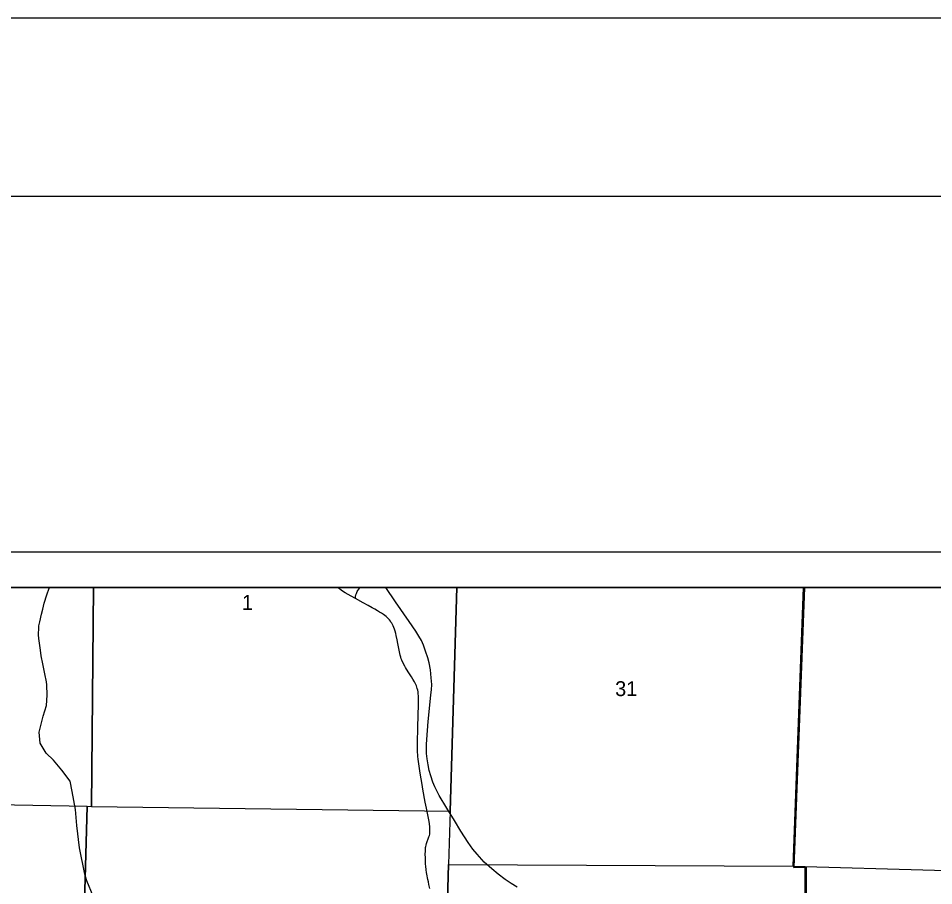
# Model space of a CAD drawing. Extents: x 0 to 34, y 0 to 22.
# Drawn here: x 4.079 to 6.653, y 19.561 to 22 of the extents above; entities that cross this region are included whole.
import ezdxf

# ---------------------------------------------------------------- set-up
doc = ezdxf.new("R2010")
doc.units = 0
for name, color, linetype in [('GM_X_Corporation', 7, 'Continuous'), ('GM_X_County_Road', 7, 'Continuous'), ('GM_X_Rail_Line', 7, 'Continuous'), ('GM_X_Section_Text', 7, 'Continuous'), ('GM_X_State_Route', 7, 'Continuous'), ('GM_X_Township_Road', 7, 'Continuous'), ('SH_Border', 7, 'Continuous'), ('SH_Cut_Line', 7, 'Continuous'), ('SH_Data', 7, 'Continuous')]:
    doc.layers.add(name, color=color, linetype=linetype)

msp = doc.modelspace()

# ---------------------------------------------------------------- linework, layer by layer
at = {"layer": 'GM_X_Corporation'}
for points in [[(9.4, 16.4853), (9.4, 20.4), (2.6, 20.4), (2.6, 16.6918), (3.1555, 16.6686), (3.1684, 16.6682), (4.0515, 16.6368), (4.1011, 16.6362), (4.1867, 16.6352), (4.5473, 16.6256), (4.6351, 16.6229), (5.4202, 16.5982), (6.0834, 16.5816), (6.2194, 16.578), (8.0963, 16.5226), (9.09, 16.4927)], [(6.2895, 20.4), (2.6, 20.4), (2.6, 16.6918), (3.1555, 16.6686), (3.1684, 16.6682), (4.0515, 16.6368), (4.1011, 16.6362), (4.1867, 16.6352), (4.5473, 16.6256), (4.6351, 16.6229), (5.4202, 16.5982), (6.0834, 16.5816), (6.2194, 16.578), (6.2729, 18.2077), (6.2744, 18.4654), (6.2786, 18.5898), (6.292, 18.5898), (6.2926, 19.1539), (6.2942, 19.6131), (6.2595, 19.6124)], [(4.2908, 20.4), (3.2614, 20.4), (3.2518, 19.8039), (4.2724, 19.7849), (4.2853, 19.7839)], [(5.3118, 20.4), (4.2908, 20.4), (4.2853, 19.7839), (5.2933, 19.7705)], [(6.2866, 20.4), (5.3118, 20.4), (5.2933, 19.7705), (5.2887, 19.6211), (6.258, 19.6163)], [(9.4, 16.4853), (9.4, 20.4), (6.2895, 20.4), (6.2595, 19.6124), (6.2942, 19.6131), (6.2926, 19.1539), (6.292, 18.5898), (6.2786, 18.5898), (6.2744, 18.4654), (6.2729, 18.2077), (6.2194, 16.578), (8.0963, 16.5226), (9.09, 16.4927)], [(7.307, 20.4), (6.2866, 20.4), (6.258, 19.6163), (6.2913, 19.615), (7.2834, 19.5867)], [(3.2518, 19.8039), (4.2724, 19.7849), (4.2417, 18.6679), (3.2101, 18.7098), (3.226, 19.805)], [(4.2853, 19.7839), (5.2933, 19.7705), (5.2887, 19.6211), (5.2602, 18.6174), (4.2417, 18.6679), (4.2724, 19.7849)], [(6.258, 19.6163), (6.2913, 19.615), (6.2882, 18.592), (6.2734, 18.5913), (5.2602, 18.6174), (5.2887, 19.6211)], [(6.2913, 19.615), (7.2834, 19.5867), (7.3046, 19.5855), (7.291, 18.5737), (6.2882, 18.592)]]:
    msp.add_lwpolyline(points, close=True, dxfattribs=at)
at = {"layer": 'GM_X_County_Road'}
msp.add_lwpolyline([(4.2897, 19.5316), (4.2723, 19.5751), (4.2662, 19.5935), (4.2513, 19.668), (4.2434, 19.7301), (4.2402, 19.7749), (4.2307, 19.8259), (4.2247, 19.8554), (4.2019, 19.8862), (4.1781, 19.9138), (4.1578, 19.934), (4.1403, 19.9623), (4.1381, 19.9924), (4.1495, 20.0381), (4.1584, 20.0679), (4.1604, 20.097), (4.1597, 20.1259), (4.1585, 20.1341), (4.1537, 20.1567), (4.1479, 20.1851), (4.1436, 20.2072), (4.1413, 20.2229), (4.1372, 20.2558), (4.1363, 20.2662), (4.1367, 20.2867), (4.1374, 20.2915), (4.1396, 20.3033), (4.1444, 20.3244), (4.1479, 20.3387), (4.1521, 20.3552), (4.1597, 20.3794), (4.1662, 20.3974), (4.1672, 20.4)], dxfattribs=at)
at = {"layer": 'GM_X_Rail_Line'}
msp.add_lwpolyline([(5.4815, 19.5569), (5.4649, 19.5671), (5.4482, 19.5782), (5.4285, 19.5933), (5.4102, 19.6081), (5.389, 19.6276), (5.3692, 19.6496), (5.3568, 19.664), (5.3437, 19.6824), (5.3232, 19.7141), (5.3053, 19.7445), (5.284, 19.7794), (5.2628, 19.8143), (5.2504, 19.8388), (5.2448, 19.8522), (5.2392, 19.8703), (5.2346, 19.8846), (5.2312, 19.9011), (5.2288, 19.9175), (5.227, 19.9326), (5.2265, 19.948), (5.2267, 19.9583), (5.228, 19.9718), (5.2312, 20.0224), (5.2357, 20.0684), (5.2393, 20.0978), (5.2409, 20.1117), (5.2413, 20.1269), (5.2403, 20.1459), (5.2376, 20.1677), (5.2347, 20.1875), (5.2303, 20.2021), (5.2239, 20.2207), (5.2182, 20.2374), (5.2123, 20.2505), (5.2056, 20.2629), (5.1967, 20.2771), (5.1783, 20.3035), (5.1399, 20.359), (5.1123, 20.4)], dxfattribs=at)
at = {"layer": 'GM_X_State_Route'}
for points in [[(5.2018, 19.969), (5.2021, 19.9991), (5.2026, 20.0143), (5.2031, 20.0321), (5.2036, 20.0491), (5.2039, 20.0608), (5.2041, 20.0716), (5.2043, 20.0834), (5.204, 20.0962), (5.2038, 20.0993), (5.2035, 20.1026), (5.2029, 20.1064), (5.202, 20.1111), (5.2007, 20.1155), (5.1996, 20.1192), (5.1982, 20.1232), (5.1965, 20.1272), (5.195, 20.1306), (5.1929, 20.1345), (5.1886, 20.142), (5.1842, 20.1488), (5.1757, 20.1622), (5.1677, 20.1747), (5.1655, 20.1787), (5.1602, 20.1886), (5.1575, 20.1951), (5.156, 20.1991), (5.1543, 20.204), (5.153, 20.2089), (5.1499, 20.2235), (5.1483, 20.2327), (5.1466, 20.2418), (5.1445, 20.2527), (5.1418, 20.2646), (5.1404, 20.2705), (5.1387, 20.2767), (5.1369, 20.2824), (5.1351, 20.2872), (5.1332, 20.2915), (5.1311, 20.2958), (5.1289, 20.2996), (5.1269, 20.3025), (5.1252, 20.305), (5.1224, 20.3085), (5.1195, 20.3118), (5.1163, 20.3151), (5.1133, 20.3179), (5.1099, 20.3206), (5.1058, 20.3237), (5.1005, 20.3273), (5.0951, 20.3306), (5.0887, 20.3344), (5.0812, 20.3385), (5.0736, 20.3427), (5.0627, 20.3485), (5.0488, 20.3562), (5.0269, 20.3686), (5.0154, 20.3751), (4.9978, 20.3848), (4.9909, 20.389), (4.9866, 20.3921), (4.9824, 20.3954), (4.9789, 20.3986), (4.9778, 20.4)], [(5.2362, 19.5532), (5.2337, 19.5645), (5.2322, 19.572), (5.2308, 19.5785), (5.228, 19.5932), (5.2272, 19.598), (5.2261, 19.6053), (5.2249, 19.6158), (5.2244, 19.6217), (5.224, 19.6296), (5.2235, 19.6411), (5.2233, 19.6478), (5.2235, 19.66), (5.2237, 19.6641), (5.2241, 19.6681), (5.2248, 19.6716), (5.2258, 19.6753), (5.2272, 19.6796), (5.2337, 19.6984), (5.2349, 19.7024), (5.2358, 19.7062), (5.2363, 19.7099), (5.2366, 19.7142), (5.2362, 19.7276), (5.234, 19.7414), (5.2311, 19.7561), (5.2293, 19.7652), (5.2264, 19.7794), (5.2232, 19.7957), (5.2165, 19.8328), (5.2144, 19.8457), (5.2117, 19.8617), (5.2093, 19.8776), (5.2063, 19.8973), (5.2035, 19.9168), (5.2027, 19.9244), (5.2016, 19.9415), (5.2015, 19.9489), (5.2018, 19.969)]]:
    msp.add_lwpolyline(points, dxfattribs=at)
at = {"layer": 'GM_X_Township_Road'}
msp.add_lwpolyline([(5.0269, 20.3686), (5.0276, 20.374), (5.0285, 20.3785), (5.0297, 20.3831), (5.0309, 20.3858), (5.0322, 20.3882), (5.0338, 20.3907), (5.0367, 20.3947), (5.0393, 20.3986), (5.0404, 20.4)], dxfattribs=at)
at = {"layer": 'SH_Border'}
msp.add_lwpolyline([(1.5, 21.5), (33.5, 21.5), (33.5, 0.5), (1.5, 0.5)], close=True, dxfattribs=at)
at = {"layer": 'SH_Cut_Line'}
msp.add_lwpolyline([(0, 0), (34, 0), (34, 22), (0, 22)], close=True, dxfattribs=at)
at = {"layer": 'SH_Data'}
for points in [[(2.5, 20.5), (9.5, 20.5), (9.5, 13.5), (2.5, 13.5)], [(2.6, 20.4), (9.4, 20.4), (9.4, 13.6), (2.6, 13.6)]]:
    msp.add_lwpolyline(points, close=True, dxfattribs=at)

# ---------------------------------------------------------------- texts
at = {"layer": 'GM_X_Section_Text'}
for s, height, p in [('1', 0.0419, (4.7079, 20.3367)), ('31', 0.04186, (5.7571, 20.0942))]:
    msp.add_text(s, height=height, rotation=0, dxfattribs=at).set_placement(p)

doc.saveas('drawing.dxf')
